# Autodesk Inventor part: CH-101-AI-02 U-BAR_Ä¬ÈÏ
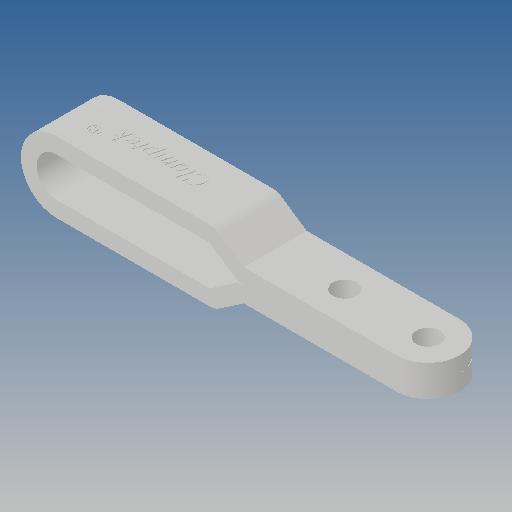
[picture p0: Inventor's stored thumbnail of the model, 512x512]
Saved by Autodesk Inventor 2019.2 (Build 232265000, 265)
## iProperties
Created: 2010-06
Part Number: CH-101-AI-02 U-BAR_Ä¬ÈÏ
Material: Ogólny
Document SubType Name: Modeling
Designer: CADENGINEERING4
Density: 1 g/cm^3
Appearance: Domyślna
Author: CADENGINEERING4
Revision Number: ÈÎºÎ
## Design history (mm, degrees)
feature "NONE"
feature "NONE:1"
node "Bryła1"
node "Bryła2"
